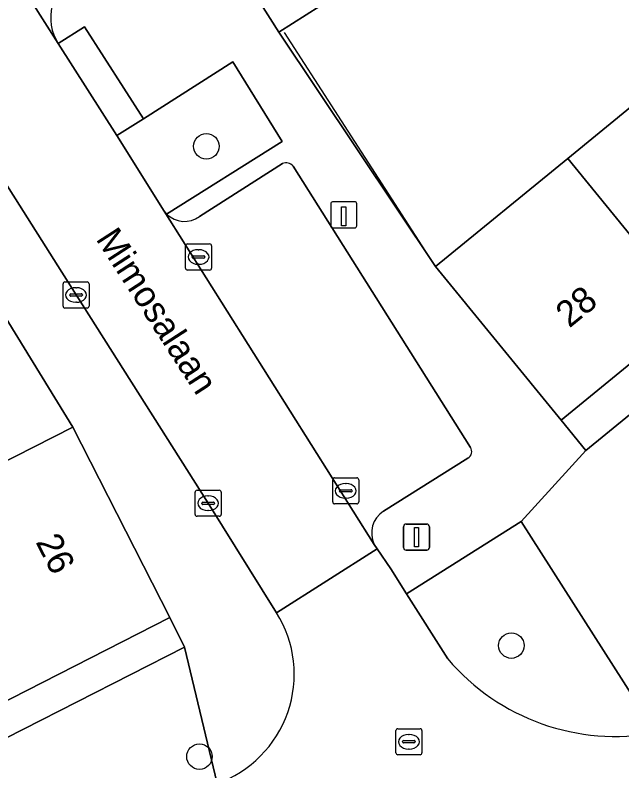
# Model space of a CAD drawing. Extents: x 162344 to 162869, y 381217 to 381818.
# Drawn here: x 162526.14 to 162549.42, y 381544.34 to 381573.33 of the extents above; entities that cross this region are included whole.
import ezdxf

# ---------------------------------------------------------------- set-up
doc = ezdxf.new("R2010")
doc.units = 0
for name, color, linetype in [('IMGEO_Boom', 7, 'Continuous'), ('IMGEO_Erf', 7, 'Continuous'), ('IMGEO_Groenvoorziening', 7, 'Continuous'), ('IMGEO_Kolk', 7, 'Continuous'), ('IMGEO_Laadpaal', 7, 'Continuous'), ('IMGEO_Lichtmast', 7, 'Continuous'), ('IMGEO_Muur', 7, 'Continuous'), ('IMGEO_Openbare_ruimte_label', 7, 'Continuous'), ('IMGEO_Pand', 7, 'Continuous'), ('IMGEO_Pand_nummerreeks', 7, 'Continuous'), ('IMGEO_Parkeervlak_open', 7, 'Continuous'), ('IMGEO_Rijbaan_lokaal_open', 7, 'Continuous'), ('IMGEO_Rioolput', 7, 'Continuous'), ('IMGEO_Voetpad_open', 7, 'Continuous')]:
    doc.layers.add(name, color=color, linetype=linetype)

msp = doc.modelspace()

# ---------------------------------------------------------------- linework, layer by layer
at = {"layer": 'IMGEO_Boom'}
for centre in [(162533.479, 381568.295), (162545.178, 381549.147), (162533.215, 381544.889)]:
    msp.add_circle(centre, 0.489, dxfattribs=at)
at = {"layer": 'IMGEO_Erf'}
for points in [[(162583.699, 381585.765), (162582.764, 381586.934), (162577.44, 381582.586), (162572.364, 381578.439), (162567.297, 381574.3), (162562.308, 381570.225), (162557.253, 381566.096), (162552.155, 381561.932), (162547.084, 381557.79), (162548.034, 381556.624)], [(162523.625, 381555.117), (162523.899, 381555.258), (162528.355, 381557.526), (162525.538, 381562.087), (162523.706, 381560.928), (162521.196, 381564.895), (162516.921, 381562.142), (162518.128, 381560.24), (162514.176, 381557.73), (162510.117, 381555.152), (162508.942, 381557.004), (162506.422, 381555.381), (162507.493, 381553.553), (162503.446, 381551.184), (162506.006, 381546.152), (162510.497, 381548.437), (162517.175, 381551.836)], [(162532.638, 381549.091), (162532.073, 381550.22), (162525.378, 381546.813), (162520.892, 381544.53), (162516.259, 381542.172), (162509.427, 381538.695), (162509.986, 381537.559)]]:
    msp.add_lwpolyline(points, close=True, dxfattribs=at)
msp.add_lwpolyline([(162540.977, 381575.683), (162536.254, 381572.675), (162542.267, 381563.687), (162547.338, 381567.829), (162552.436, 381571.993), (162557.491, 381576.122)], dxfattribs=at)
at = {"layer": 'IMGEO_Groenvoorziening'}
msp.add_lwpolyline([(162534.495, 381571.53), (162531.065, 381569.354), (162530.041, 381568.705), (162531.859, 381565.804), (162531.951, 381565.699), (162536.382, 381568.48)], close=True, dxfattribs=at)
for points in [[(162550.719, 381545.809), (162545.554, 381553.9), (162541.16, 381551.133)], [(162541.16, 381551.133), (162542.738, 381548.636)]]:
    msp.add_lwpolyline(points, dxfattribs=at)
msp.add_arc((162549.16, 381554.086), 8.422, 220.3194, 280.6706, dxfattribs=at)
at = {"layer": 'IMGEO_Kolk'}
for p, q in [((162532.678, 381563.624), (162532.678, 381564.476)), ((162532.753, 381564.55), (162533.605, 381564.55)), ((162533.679, 381564.476), (162533.679, 381563.624)), ((162533.166, 381564.33), (162533.191, 381564.33)), ((162532.937, 381564.044), (162532.937, 381564.056)), ((162533.375, 381564.007), (162532.977, 381564.007)), ((162532.98, 381564.093), (162533.378, 381564.093)), ((162533.421, 381564.056), (162533.421, 381564.044)), ((162533.189, 381563.77), (162533.164, 381563.77)), ((162533.605, 381563.55), (162532.753, 381563.55)), ((162527.981, 381562.168), (162527.981, 381563.02)), ((162528.056, 381563.094), (162528.908, 381563.094)), ((162528.982, 381563.02), (162528.982, 381562.168)), ((162528.469, 381562.874), (162528.494, 381562.874)), ((162528.24, 381562.588), (162528.24, 381562.6)), ((162528.678, 381562.551), (162528.28, 381562.551)), ((162528.283, 381562.637), (162528.681, 381562.637)), ((162528.724, 381562.6), (162528.724, 381562.588)), ((162528.492, 381562.314), (162528.467, 381562.314)), ((162528.908, 381562.094), (162528.056, 381562.094)), ((162538.325, 381554.655), (162538.325, 381555.507)), ((162538.4, 381555.581), (162539.252, 381555.581)), ((162539.326, 381555.507), (162539.326, 381554.655)), ((162538.813, 381555.361), (162538.838, 381555.361)), ((162533.047, 381554.179), (162533.047, 381555.031)), ((162533.122, 381555.105), (162533.974, 381555.105)), ((162533.535, 381554.885), (162533.56, 381554.885)), ((162534.048, 381555.031), (162534.048, 381554.179)), ((162538.584, 381555.075), (162538.584, 381555.087)), ((162539.022, 381555.038), (162538.624, 381555.038)), ((162538.627, 381555.124), (162539.025, 381555.124)), ((162539.068, 381555.087), (162539.068, 381555.075)), ((162533.306, 381554.599), (162533.306, 381554.611)), ((162533.349, 381554.648), (162533.747, 381554.648)), ((162533.79, 381554.611), (162533.79, 381554.599)), ((162538.836, 381554.801), (162538.811, 381554.801)), ((162533.744, 381554.562), (162533.346, 381554.562)), ((162533.558, 381554.325), (162533.533, 381554.325)), ((162539.252, 381554.581), (162538.4, 381554.581)), ((162533.974, 381554.105), (162533.122, 381554.105))]:
    msp.add_line(p, q, dxfattribs=at)
for points in [[(162532.678, 381563.624), (162532.678, 381564.476)], [(162532.753, 381564.55), (162533.605, 381564.55)], [(162533.679, 381564.476), (162533.679, 381563.624)], [(162533.605, 381563.55), (162532.753, 381563.55)], [(162527.981, 381562.168), (162527.981, 381563.02)], [(162528.056, 381563.094), (162528.908, 381563.094)], [(162528.982, 381563.02), (162528.982, 381562.168)], [(162528.908, 381562.094), (162528.056, 381562.094)], [(162538.325, 381554.655), (162538.325, 381555.507)], [(162538.4, 381555.581), (162539.252, 381555.581)], [(162539.326, 381555.507), (162539.326, 381554.655)], [(162533.047, 381554.179), (162533.047, 381555.031)], [(162533.122, 381555.105), (162533.974, 381555.105)], [(162534.048, 381555.031), (162534.048, 381554.179)], [(162539.252, 381554.581), (162538.4, 381554.581)], [(162533.974, 381554.105), (162533.122, 381554.105)]]:
    msp.add_lwpolyline(points, dxfattribs=at)
for centre, radius, start, end in [((162532.755, 381564.474), 0.0765, 91.552, 178.448), ((162532.755, 381564.474), 0.0765, 91.552, 178.448), ((162533.603, 381564.474), 0.0765, 1.552, 88.448), ((162533.603, 381564.474), 0.0765, 1.552, 88.448), ((162532.977, 381564.053), 0.0403, 85.8775, 175.7526), ((162532.974, 381564.043), 0.0366, 178.938, 274.7102), ((162533.378, 381564.05), 0.043, 264.8664, 352.4533), ((162533.382, 381564.055), 0.0386, 1.7309, 96.639), ((162532.755, 381563.626), 0.0765, 181.552, 268.448), ((162532.755, 381563.626), 0.0765, 181.552, 268.448), ((162533.603, 381563.626), 0.0765, 271.552, 358.448), ((162533.603, 381563.626), 0.0765, 271.552, 358.448), ((162528.058, 381563.018), 0.0765, 91.552, 178.448), ((162528.058, 381563.018), 0.0765, 91.552, 178.448), ((162528.906, 381563.018), 0.0765, 1.552, 88.448), ((162528.906, 381563.018), 0.0765, 1.552, 88.448), ((162528.28, 381562.597), 0.0403, 85.8775, 175.7526), ((162528.277, 381562.587), 0.0366, 178.938, 274.7102), ((162528.681, 381562.594), 0.043, 264.8664, 352.4533), ((162528.685, 381562.599), 0.0386, 1.7309, 96.639), ((162528.058, 381562.17), 0.0765, 181.552, 268.448), ((162528.058, 381562.17), 0.0765, 181.552, 268.448), ((162528.906, 381562.17), 0.0765, 271.552, 358.448), ((162528.906, 381562.17), 0.0765, 271.552, 358.448), ((162538.402, 381555.505), 0.0765, 91.552, 178.448), ((162538.402, 381555.505), 0.0765, 91.552, 178.448), ((162539.25, 381555.505), 0.0765, 1.552, 88.448), ((162539.25, 381555.505), 0.0765, 1.552, 88.448), ((162533.124, 381555.029), 0.0765, 91.552, 178.448), ((162533.124, 381555.029), 0.0765, 91.552, 178.448), ((162533.972, 381555.029), 0.0765, 1.552, 88.448), ((162533.972, 381555.029), 0.0765, 1.552, 88.448), ((162538.624, 381555.084), 0.0403, 85.8775, 175.7526), ((162538.621, 381555.074), 0.0366, 178.938, 274.7102), ((162539.025, 381555.081), 0.043, 264.8664, 352.4533), ((162539.029, 381555.086), 0.0386, 1.7309, 96.639), ((162533.346, 381554.608), 0.0403, 85.8775, 175.7526), ((162533.343, 381554.598), 0.0366, 178.938, 274.7102), ((162533.747, 381554.605), 0.043, 264.8664, 352.4533), ((162533.751, 381554.61), 0.0386, 1.7309, 96.639), ((162538.402, 381554.657), 0.0765, 181.552, 268.448), ((162538.402, 381554.657), 0.0765, 181.552, 268.448), ((162539.25, 381554.657), 0.0765, 271.552, 358.448), ((162539.25, 381554.657), 0.0765, 271.552, 358.448), ((162533.124, 381554.181), 0.0765, 181.552, 268.448), ((162533.124, 381554.181), 0.0765, 181.552, 268.448), ((162533.972, 381554.181), 0.0765, 271.552, 358.448), ((162533.972, 381554.181), 0.0765, 271.552, 358.448)]:
    msp.add_arc(centre, radius, start, end, dxfattribs=at)
for centre, major_axis, ratio, start_param, end_param in [((162533.165, 381564.05), (-0.387, 0.002), 0.722429, 4.712389, 7.853982), ((162533.19, 381564.05), (-0.39, 0.002), 0.717154, 1.570796, 4.712389), ((162528.468, 381562.594), (-0.387, 0.002), 0.722429, 4.712389, 7.853982), ((162528.493, 381562.594), (-0.39, 0.002), 0.717154, 1.570796, 4.712389), ((162538.812, 381555.081), (-0.387, 0.002), 0.722429, 4.712389, 7.853982), ((162538.837, 381555.081), (-0.39, 0.002), 0.717154, 1.570796, 4.712389), ((162533.534, 381554.605), (-0.387, 0.002), 0.722429, 4.712389, 7.853982), ((162533.559, 381554.605), (-0.39, 0.002), 0.717154, 1.570796, 4.712389)]:
    msp.add_ellipse(centre, major_axis=major_axis, ratio=ratio, start_param=start_param, end_param=end_param, dxfattribs=at)
at = {"layer": 'IMGEO_Laadpaal'}
for p, q in [((162538.248, 381566.083), (162538.248, 381565.242)), ((162538.248, 381566.083), (162538.248, 381565.242)), ((162539.164, 381566.167), (162538.323, 381566.167)), ((162539.164, 381566.167), (162538.323, 381566.167)), ((162539.248, 381565.251), (162539.248, 381566.092)), ((162539.248, 381565.251), (162539.248, 381566.092)), ((162538.332, 381565.167), (162539.173, 381565.167)), ((162538.332, 381565.167), (162539.173, 381565.167))]:
    msp.add_line(p, q, dxfattribs=at)
msp.add_lwpolyline([(162538.663, 381565.98), (162538.823, 381565.98), (162538.823, 381565.247), (162538.663, 381565.247), (162538.663, 381565.98)], dxfattribs=at)
for centre, start, end in [((162538.326, 381566.089), 92.4484, 184.2845), ((162538.326, 381566.089), 92.4484, 184.2845), ((162539.17, 381566.089), 2.4484, 94.2845), ((162539.17, 381566.089), 2.4484, 94.2845), ((162538.326, 381565.245), 182.4484, 274.2845), ((162538.326, 381565.245), 182.4484, 274.2845), ((162539.17, 381565.245), 272.4484, 4.2845), ((162539.17, 381565.245), 272.4484, 4.2845)]:
    msp.add_arc(centre, 0.0779, start, end, dxfattribs=at)
at = {"layer": 'IMGEO_Lichtmast'}
for p, q in [((162541.143, 381553.806), (162541.933, 381553.806)), ((162541.933, 381553.806), (162541.143, 381553.806)), ((162541.043, 381552.906), (162541.043, 381553.706)), ((162541.043, 381553.706), (162541.043, 381552.906)), ((162542.033, 381553.706), (162542.033, 381552.906)), ((162542.033, 381552.906), (162542.033, 381553.706)), ((162541.933, 381552.806), (162541.143, 381552.806)), ((162541.143, 381552.806), (162541.933, 381552.806))]:
    msp.add_line(p, q, dxfattribs=at)
msp.add_lwpolyline([(162541.463, 381553.681), (162541.613, 381553.681), (162541.613, 381552.931), (162541.463, 381552.931), (162541.463, 381553.681)], dxfattribs=at)
for centre, start, end in [((162541.143, 381553.706), 90, 180), ((162541.143, 381553.706), 90, 180), ((162541.933, 381553.706), 0, 90), ((162541.933, 381553.706), 360, 90), ((162541.143, 381552.906), 180, 270), ((162541.143, 381552.906), 180, 270), ((162541.933, 381552.906), 270, 0), ((162541.933, 381552.906), 270, 0)]:
    msp.add_arc(centre, 0.1, start, end, dxfattribs=at)
at = {"layer": 'IMGEO_Muur'}
for points in [[(162542.267, 381563.687), (162536.475, 381572.66)], [(162528.355, 381557.526), (162525.538, 381562.087)]]:
    msp.add_lwpolyline(points, dxfattribs=at)
at = {"layer": 'IMGEO_Pand'}
for points in [[(162540.977, 381575.683), (162539.372, 381578.205), (162534.661, 381575.207), (162536.254, 381572.675)], [(162552.436, 381571.993), (162547.338, 381567.829), (162552.155, 381561.932), (162557.253, 381566.096)], [(162547.338, 381567.829), (162542.267, 381563.687), (162547.084, 381557.79), (162552.155, 381561.932)], [(162525.378, 381546.813), (162532.073, 381550.22), (162528.355, 381557.526), (162523.899, 381555.258), (162523.625, 381555.117), (162525.484, 381551.465), (162523.52, 381550.466)]]:
    msp.add_lwpolyline(points, close=True, dxfattribs=at)
at = {"layer": 'IMGEO_Parkeervlak_open'}
for points in [[(162508.323, 381602.896), (162527.79, 381572.233)], [(162536.402, 381567.631), (162533.221, 381565.602)], [(162543.607, 381556.75), (162536.805, 381567.533)], [(162531.951, 381565.699), (162531.859, 381565.804), (162539.912, 381553.029)], [(162540.274, 381554.304), (162543.511, 381556.337)]]:
    msp.add_lwpolyline(points, dxfattribs=at)
for centre, radius, start, end in [((162529.375, 381573.217), 1.865, 165.4943, 211.8258), ((162536.539, 381567.317), 0.343, 39.0893, 113.5754), ((162532.643, 381566.4), 0.985, 225.3647, 305.9), ((162543.37, 381556.587), 0.287, 299.4015, 34.4269), ((162540.828, 381553.458), 1.011, 123.2016, 205.0976)]:
    msp.add_arc(centre, radius, start, end, dxfattribs=at)
at = {"layer": 'IMGEO_Rijbaan_lokaal_open'}
msp.add_lwpolyline([(162508.323, 381602.896), (162508.241, 381602.992), (162508.054, 381603.286), (162504.221, 381600.859), (162509.771, 381592.107), (162519.683, 381576.506), (162528.482, 381562.594), (162533.548, 381554.605), (162536.173, 381550.404), (162540.033, 381552.852), (162539.912, 381553.029), (162531.859, 381565.804), (162530.041, 381568.705), (162527.79, 381572.233)], close=True, dxfattribs=at)
msp.add_lwpolyline([(162542.738, 381548.636), (162541.16, 381551.133), (162540.551, 381552.094), (162540.033, 381552.852), (162536.173, 381550.404)], dxfattribs=at)
for centre, radius, start, end in [((162532.4, 381548.048), 4.449, 289.6131, 31.9854), ((162549.16, 381554.086), 8.422, 220.3194, 280.6706)]:
    msp.add_arc(centre, radius, start, end, dxfattribs=at)
at = {"layer": 'IMGEO_Rioolput'}
for p, q in [((162540.822, 381545.959), (162541.674, 381545.959)), ((162540.747, 381545.033), (162540.747, 381545.885)), ((162541.235, 381545.739), (162541.26, 381545.739)), ((162541.748, 381545.885), (162541.748, 381545.033)), ((162541.006, 381545.453), (162541.006, 381545.465)), ((162541.444, 381545.416), (162541.046, 381545.416)), ((162541.049, 381545.502), (162541.447, 381545.502)), ((162541.49, 381545.465), (162541.49, 381545.453)), ((162541.258, 381545.179), (162541.233, 381545.179)), ((162541.674, 381544.959), (162540.822, 381544.959))]:
    msp.add_line(p, q, dxfattribs=at)
for points in [[(162540.822, 381545.959), (162541.674, 381545.959)], [(162540.747, 381545.033), (162540.747, 381545.885)], [(162541.748, 381545.885), (162541.748, 381545.033)], [(162541.674, 381544.959), (162540.822, 381544.959)]]:
    msp.add_lwpolyline(points, dxfattribs=at)
for centre, radius, start, end in [((162540.824, 381545.883), 0.0765, 91.552, 178.448), ((162540.824, 381545.883), 0.0765, 91.552, 178.448), ((162541.672, 381545.883), 0.0765, 1.552, 88.448), ((162541.672, 381545.883), 0.0765, 1.552, 88.448), ((162541.046, 381545.462), 0.0403, 85.8775, 175.7526), ((162541.043, 381545.452), 0.0366, 178.938, 274.7102), ((162541.447, 381545.459), 0.043, 264.8664, 352.4533), ((162541.451, 381545.464), 0.0386, 1.7309, 96.639), ((162540.824, 381545.035), 0.0765, 181.552, 268.448), ((162540.824, 381545.035), 0.0765, 181.552, 268.448), ((162541.672, 381545.035), 0.0765, 271.552, 358.448), ((162541.672, 381545.035), 0.0765, 271.552, 358.448)]:
    msp.add_arc(centre, radius, start, end, dxfattribs=at)
for centre, major_axis, ratio, start_param, end_param in [((162541.234, 381545.459), (-0.387, 0.002), 0.722429, 4.712389, 7.853982), ((162541.259, 381545.459), (-0.39, 0.002), 0.717154, 1.570796, 4.712389)]:
    msp.add_ellipse(centre, major_axis=major_axis, ratio=ratio, start_param=start_param, end_param=end_param, dxfattribs=at)
at = {"layer": 'IMGEO_Voetpad_open'}
for points in [[(162472.704, 381650.202), (162472.225, 381650.761), (162464.301, 381660.45), (162461.143, 381664.345), (162453.433, 381673.852), (162452.016, 381672.565), (162460.935, 381661.289), (162471.067, 381648.837), (162472.56, 381646.493), (162481.795, 381631.988), (162482.857, 381630.326), (162500, 381603.428), (162522.094, 381568.761), (162522.773, 381567.696), (162523.584, 381566.423), (162523.028, 381566.054), (162525.538, 381562.087), (162528.355, 381557.526), (162532.073, 381550.22), (162532.638, 381549.091), (162533.893, 381543.857)], [(162536.254, 381572.675), (162534.661, 381575.207), (162533.863, 381576.458), (162531.035, 381574.671), (162500, 381623.471), (162483.717, 381649.074), (162486.625, 381650.919), (162489.805, 381652.936), (162488.804, 381654.132), (162487.93, 381655.177), (162482.537, 381650.933), (162479.032, 381656.467), (162483.97, 381660.263), (162483.121, 381661.563), (162478.205, 381657.739), (162476.197, 381660.891)], [(162536.173, 381550.404), (162533.548, 381554.605), (162528.482, 381562.594), (162519.683, 381576.506), (162509.771, 381592.107), (162504.221, 381600.859), (162502.811, 381603.082), (162500.464, 381606.783), (162491.687, 381620.613), (162482.235, 381635.536), (162480.538, 381638.212), (162479.529, 381637.56), (162475.997, 381643.106), (162473.959, 381646.306)], [(162533.181, 381543.553), (162533.404, 381543.643), (162533.689, 381543.768), (162533.893, 381543.857), (162532.638, 381549.091), (162509.986, 381537.559), (162508.501, 381536.927), (162507.307, 381539.243), (162497.363, 381534.965), (162497.202, 381535.283), (162493.857, 381533.592), (162493.913, 381533.481), (162493.347, 381533.215), (162453.435, 381611.809), (162453.968, 381612.034), (162453.886, 381612.196), (162461.304, 381615.919), (162461.371, 381615.787), (162465.983, 381618.274)], [(162590.428, 381581.301), (162585.923, 381586.92), (162583.699, 381585.765), (162548.034, 381556.624), (162545.554, 381553.9), (162550.719, 381545.809)], [(162527.79, 381572.233), (162528.798, 381572.881), (162531.065, 381569.354), (162534.495, 381571.53), (162536.382, 381568.48), (162531.951, 381565.699)], [(162539.912, 381553.029), (162540.033, 381552.852), (162540.551, 381552.094), (162541.16, 381551.133), (162545.554, 381553.9), (162548.034, 381556.624), (162547.084, 381557.79), (162542.267, 381563.687), (162536.254, 381572.675)], [(162533.221, 381565.602), (162536.402, 381567.631)], [(162536.805, 381567.533), (162543.607, 381556.75)], [(162543.511, 381556.337), (162540.274, 381554.304)]]:
    msp.add_lwpolyline(points, dxfattribs=at)
msp.add_lwpolyline([(162528.798, 381572.881), (162527.79, 381572.233), (162530.041, 381568.705), (162531.065, 381569.354)], close=True, dxfattribs=at)
for centre, radius, start, end in [((162529.375, 381573.217), 1.865, 165.4943, 211.8258), ((162536.539, 381567.317), 0.343, 39.0893, 113.5754), ((162532.643, 381566.4), 0.985, 225.3647, 305.9), ((162543.37, 381556.587), 0.287, 299.4015, 34.4269), ((162540.828, 381553.458), 1.011, 123.2016, 205.0976), ((162532.4, 381548.048), 4.449, 289.6131, 31.9854)]:
    msp.add_arc(centre, radius, start, end, dxfattribs=at)

# ---------------------------------------------------------------- texts
at = {"layer": 'IMGEO_Openbare_ruimte_label'}
msp.add_text('Mimosalaan', height=1, rotation=302.8798, dxfattribs=at).set_placement((162529.217, 381564.744))
at = {"layer": 'IMGEO_Pand_nummerreeks'}
for s, rotation, p in [('28', 39.2425, (162547.401, 381561.303)), ('26', 296.9714, (162526.916, 381553.122))]:
    msp.add_text(s, height=1, rotation=rotation, dxfattribs=at).set_placement(p)

doc.saveas('drawing.dxf')
